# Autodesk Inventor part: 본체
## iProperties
Created: 2015-03
Part Number: 본체
Document SubType Name: Modeling
Designer: elite
Density: 2.71 g/cm^3
Material: 알루미늄-6061
Mass: 450.699 g
Surface Area: 332.701 cm^2
Volume: 166.31 cm^3
Author: elite
